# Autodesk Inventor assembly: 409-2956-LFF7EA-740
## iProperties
Created: 2010-09
Part Number: 409-2956-LFF7EA-740
Document SubType Name: Weldment
Designer: S. Boerckel
Weld Material: Welded Steel Mild
Mass: 33307.8 g
Surface Area: 13379.1 cm^2
Volume: 4229.16 cm^3
Density: 7.87574 g/cm^3
Description: DISCHARGE SPOOL
User Status: WELD
Material: WELDMENT
SMR: =<MATERIAL>
Author: S. Boerckel
Revision Number: B
